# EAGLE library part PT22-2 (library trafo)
TRANSFORMER 1 primary winding, temp. protection fuse, 2 secondary windings, mounting holes BLOCK
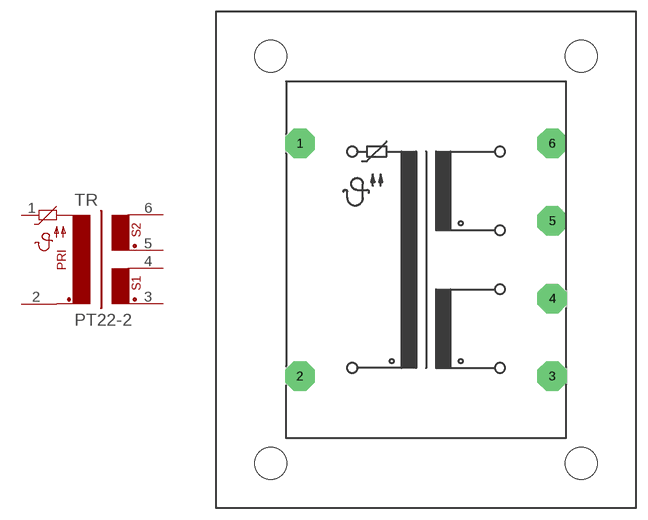
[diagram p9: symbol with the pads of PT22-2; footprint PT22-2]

Designator prefix TR

## PT22-2  [PT22-2]
1  1  pas
2  2  pas
3  3  pas
4  4  pas
5  5  pas
6  6  pas

## Footprint PT22-2 (pad centres in mm)
TRANSFORMER 1 primary winding, 2 secondary windings, temp. protection fuse, mounting holes
drill 1.397 pad 3.81 octagon: 1 -16.256,15.011; 2 -16.256,-15.011; 3 16.256,-15.011; 4 16.256,-5.004; 5 16.256,5.004; 6 16.256,15.011
hole 4.115 at -19.99,-26.264
hole 4.115 at -19.99,26.264
hole 4.115 at 19.99,-26.264
hole 4.115 at 19.99,26.264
